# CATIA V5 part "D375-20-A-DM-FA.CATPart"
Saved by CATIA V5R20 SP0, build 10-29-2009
Part number: D375-20-A-DM-FA
Bounding box of the stored display mesh (mm): x -16 to 0, y -10 to 10, z -10 to 10
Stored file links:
  C:\Users\Utente\Desktop\IO LAVORO\3D X SITO CF\X SITO\PLASTICA\D375\D375-20-A-DM-FA.CATPart
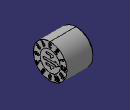
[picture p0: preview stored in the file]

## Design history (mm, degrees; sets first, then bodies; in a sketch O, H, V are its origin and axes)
Set1
  DatumSurface1 to DatumSurface216 "D375-20-A-DM-FA"
Body1 (main body)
